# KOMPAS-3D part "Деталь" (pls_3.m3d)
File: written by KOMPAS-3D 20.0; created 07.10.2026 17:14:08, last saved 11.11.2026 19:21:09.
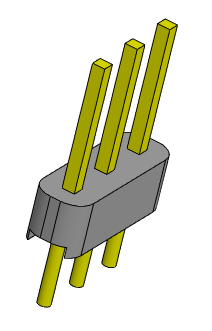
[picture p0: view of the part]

Document properties: Полное имя файла: D:\myProjects\Progect_esp32\box_compas\разъемы\pls_3.m3d

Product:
- Part/product: Деталь
    Масса: 0.000374976

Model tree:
1. Эскиз:1
2. Элемент выдавливания:1
     Расстояние 1 = 2.5
3. Эскиз:2  (with: Элемент выдавливания:1)
4. Элемент выдавливания:2
     Расстояние 1 = 6
5. Массив по сетке:1  (with: Элемент выдавливания:2, Эскиз:2)  (3 pattern instances)
     Шаг 1 = 2.54; Угол раствора = 90
6. Эскиз:3  (with: Элемент выдавливания:1)
7. Элемент выдавливания:3
     Расстояние 1 = 3
8. Массив по сетке:2  (with: Элемент выдавливания:3, Эскиз:3)  (3 pattern instances)
     Шаг 1 = 2.54; Угол раствора = 90; Геометрический массив = 128
9. Эскиз:4  (with: Элемент выдавливания:1)
10. Элемент выдавливания:4
     Расстояние 2 = 7.62
11. Скругление:1  (with: Элемент выдавливания:1)
     Радиус = 1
